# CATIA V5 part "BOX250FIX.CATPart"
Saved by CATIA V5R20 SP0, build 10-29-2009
Part number: BOX250FIX
Bounding box of the stored display mesh (mm): x 0 to 401, y -20 to 55, z -40 to 15
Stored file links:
  C:\Users\Utente\Desktop\IO LAVORO\3D X SITO CF\X SITO\PLASTICA\BOX\BOX250FIX.CATPart
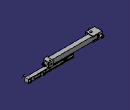
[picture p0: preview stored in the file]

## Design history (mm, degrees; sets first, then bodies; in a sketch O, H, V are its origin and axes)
Set1
  DatumSurface1 to DatumSurface16 "_ZH90/3_head"
  DatumSurface17 to DatumSurface34 "_ZH90/3_screw1"
  DatumSurface35 to DatumSurface55 "_ZH90/3_hand"
  DatumSurface56 to DatumSurface73 "_ZH90/3_screw2"
  DatumSurface74 to DatumSurface94 "_ZH90/3_he"
  DatumSurface95 to DatumSurface109 "_ZH90/3_screw3"
  DatumSurface110 to DatumSurface117 "_ZH90/3_stift1"
  DatumSurface118 to DatumSurface127 "_ZH90/3_stift2"
  DatumSurface128 to DatumSurface160 "_ZH90/04_body"
  DatumSurface161 to DatumSurface178 "_M8-5"
  DatumSurface179 to DatumSurface198 "_ST2"
  DatumSurface199 to DatumSurface213 "_ZH90/04_foot3"
  DatumSurface214 to DatumSurface230 "_M6-3"
  DatumSurface231 to DatumSurface248 "_M6-4"
  DatumSurface249 to DatumSurface260 "_ZH90/04_foot4"
  DatumSurface261 to DatumSurface280 "_ST1"
Body1 (main body)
